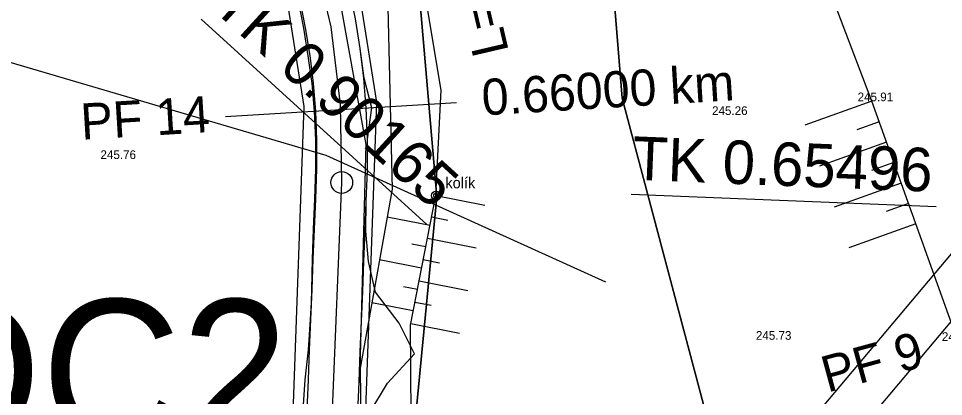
# Model space of a CAD drawing. Extents: x -555887 to -552101, y -1100251 to -1096546.
# Drawn here: x -554275.9 to -554212, y -1096964.9 to -1096938.8 of the extents above; entities that cross this region are included whole.
import ezdxf

# ---------------------------------------------------------------- set-up
doc = ezdxf.new("R2010")
doc.units = 0
for name, color, linetype in [('PARCELY_cesty', 7, 'Continuous'), ('PARCELY_VHO', 7, 'Continuous'), ('POLYGONY_POPIS_CESTY', 7, 'Continuous'), ('POLYGONY_SITUACE_PF', 7, 'Continuous'), ('POLYGONY_SITUACE_PF_POPISY', 7, 'Continuous'), ('POLYGONY_SITUACE_PO', 7, 'Continuous'), ('ram_VC2', 7, 'Continuous'), ('vrstevnice', 7, 'Continuous'), ('Výškopis', 7, 'Continuous'), ('ZSST', 7, 'Continuous'), ('zájem', 7, 'Continuous')]:
    doc.layers.add(name, color=color, linetype=linetype)

msp = doc.modelspace()

# ---------------------------------------------------------------- linework, layer by layer
for p, q in [((-554263.284, -1096938.802), (-554247.684, -1096952.999)), ((-554233.587, -1096950.895), (-554212.512, -1096951.742))]:
    msp.add_line(p, q)
at = {"layer": 'PARCELY_cesty'}
for points in [[(-554235.26, -1097250.21), (-554222.331, -1097095.103), (-554222.177, -1097088.532), (-554223.591, -1097078.803), (-554226.634, -1097069.372), (-554233.336, -1097058.257), (-554245.88, -1097042.059), (-554250.33, -1097033.26), (-554252.753, -1097025.27), (-554253.637, -1097013.936), (-554251.138, -1096944.546), (-554252.472, -1096936.15), (-554254.994, -1096928.042), (-554262.23, -1096914.12), (-554265.12, -1096907.97)], [(-554240.159, -1097243.281), (-554227.326, -1097094.829), (-554227.186, -1097088.835), (-554228.479, -1097079.938), (-554231.215, -1097071.458), (-554237.468, -1097061.088), (-554250.126, -1097044.743), (-554254.988, -1097035.128), (-554257.695, -1097026.201), (-554258.644, -1097014.04), (-554256.152, -1096944.852), (-554257.354, -1096937.291), (-554259.63, -1096929.971), (-554262.611, -1096924.345), (-554273.038, -1096923.935)]]:
    msp.add_lwpolyline(points, dxfattribs=at)
at = {"layer": 'PARCELY_VHO'}
for points in [[(-554130.46, -1097180.06), (-554159.17, -1097101.34), (-554159.64, -1097082.93), (-554163.72, -1097067.19), (-554173.74, -1097050.79), (-554190.63, -1097034.96), (-554197.16, -1097028.05), (-554217.46, -1096987.98), (-554225.33, -1096977.64), (-554234.21, -1096944.26), (-554236.99, -1096909.92), (-554235.22, -1096898.62), (-554228.6, -1096882.13), (-554225.73, -1096869.26), (-554224.9, -1096864.61), (-554220.11, -1096846.63), (-554200.4, -1096831.93), (-554179.17, -1096807.62), (-554142.08, -1096773.53), (-554110.69, -1096747.36), (-554089.18, -1096729.49)], [(-554235.26, -1097250.21), (-554222.331, -1097095.103), (-554222.177, -1097088.532), (-554223.591, -1097078.803), (-554226.634, -1097069.372), (-554233.336, -1097058.257), (-554245.88, -1097042.059), (-554250.33, -1097033.26), (-554252.753, -1097025.27), (-554253.637, -1097013.936), (-554251.138, -1096944.546), (-554252.472, -1096936.15), (-554254.994, -1096928.042), (-554262.23, -1096914.12), (-554265.12, -1096907.97), (-554264.18, -1096901.52), (-554256.593, -1096884.824), (-554225.08, -1096837.14), (-554208.2, -1096823.7)], [(-554200.4, -1096831.93), (-554220.11, -1096846.63), (-554224.9, -1096864.61), (-554233.29, -1096868.06), (-554243.42, -1096872.22), (-554247.48, -1096879.5), (-554255.66, -1096892.57), (-554260.45, -1096913.44), (-554248.68, -1096931.61), (-554247, -1096951.09), (-554248.74, -1096969.23), (-554247.82, -1097012.49), (-554234.69, -1097042.48), (-554228.63, -1097050.04), (-554218.79, -1097074.22), (-554216.52, -1097103.52), (-554219.47, -1097120.44), (-554219.42, -1097159.44)]]:
    msp.add_lwpolyline(points, dxfattribs=at)
at = {"layer": 'POLYGONY_SITUACE_PF'}
for p, q in [((-554253.622, -1096945.055), (-554245.637, -1096944.571)), ((-554261.607, -1096945.539), (-554253.622, -1096945.055))]:
    msp.add_line(p, q, dxfattribs=at)
at = {"layer": 'POLYGONY_SITUACE_PO'}
for p, q in [((-554254.299, -1096939.346), (-554255.527, -1096934.095)), ((-554252.618, -1096938.787), (-554253.03, -1096936.758)), ((-554252.618, -1096938.787), (-554253.03, -1096936.758)), ((-554252.618, -1096938.787), (-554253.03, -1096936.758)), ((-554256.188, -1096939.439), (-554256.55, -1096937.548)), ((-554256.061, -1096939.416), (-554256.445, -1096937.524)), ((-554256.061, -1096939.416), (-554256.445, -1096937.524)), ((-554252.287, -1096940.83), (-554252.618, -1096938.787)), ((-554252.287, -1096940.83), (-554252.618, -1096938.787)), ((-554252.287, -1096940.83), (-554252.618, -1096938.787)), ((-554255.889, -1096941.34), (-554256.188, -1096939.439)), ((-554255.752, -1096941.321), (-554256.061, -1096939.416)), ((-554255.752, -1096941.321), (-554256.061, -1096939.416)), ((-554253.645, -1096944.699), (-554254.299, -1096939.346)), ((-554252.038, -1096942.885), (-554252.287, -1096940.83)), ((-554252.038, -1096942.885), (-554252.287, -1096940.83)), ((-554252.026, -1096942.884), (-554252.287, -1096940.83)), ((-554252.287, -1096940.83), (-554252.287, -1096940.83)), ((-554255.622, -1096943.247), (-554255.889, -1096941.34)), ((-554255.52, -1096943.237), (-554255.752, -1096941.321)), ((-554255.52, -1096943.237), (-554255.752, -1096941.321)), ((-554251.875, -1096944.949), (-554252.038, -1096942.885)), ((-554251.875, -1096944.949), (-554252.038, -1096942.885)), ((-554251.501, -1096944.926), (-554252.026, -1096942.884)), ((-554255.454, -1096945.166), (-554255.622, -1096943.247)), ((-554255.369, -1096945.161), (-554255.52, -1096943.237)), ((-554255.369, -1096945.161), (-554255.52, -1096943.237)), ((-554253.571, -1096950.091), (-554253.645, -1096944.699)), ((-554255.359, -1096947.171), (-554255.454, -1096945.166)), ((-554255.291, -1096947.169), (-554255.369, -1096945.161)), ((-554255.291, -1096947.169), (-554255.369, -1096945.161)), ((-554251.791, -1096947.103), (-554251.875, -1096944.949)), ((-554251.791, -1096947.103), (-554251.875, -1096944.949)), ((-554251.791, -1096947.103), (-554251.501, -1096944.926)), ((-554255.357, -1096949.178), (-554255.359, -1096947.171)), ((-554255.298, -1096949.18), (-554255.291, -1096947.169)), ((-554255.298, -1096949.18), (-554255.291, -1096947.169)), ((-554251.799, -1096949.259), (-554251.791, -1096947.103)), ((-554251.799, -1096949.259), (-554251.791, -1096947.103)), ((-554251.799, -1096949.259), (-554251.791, -1096947.103)), ((-554251.791, -1096947.103), (-554251.791, -1096947.103)), ((-554255.426, -1096951.229), (-554255.357, -1096949.178)), ((-554255.368, -1096951.231), (-554255.298, -1096949.18)), ((-554255.368, -1096951.231), (-554255.298, -1096949.18)), ((-554251.871, -1096951.372), (-554251.799, -1096949.259)), ((-554251.871, -1096951.372), (-554251.799, -1096949.259)), ((-554251.871, -1096951.372), (-554251.799, -1096949.259)), ((-554256.141, -1097013.988), (-554253.571, -1096950.091)), ((-554255.524, -1096953.31), (-554255.426, -1096951.229)), ((-554255.452, -1096953.313), (-554255.368, -1096951.231)), ((-554255.452, -1096953.313), (-554255.368, -1096951.231)), ((-554251.955, -1096953.453), (-554251.871, -1096951.372)), ((-554251.955, -1096953.453), (-554251.871, -1096951.372)), ((-554251.899, -1096953.456), (-554251.871, -1096951.372)), ((-554251.871, -1096951.372), (-554251.871, -1096951.372)), ((-554255.581, -1096955.393), (-554255.524, -1096953.31)), ((-554255.536, -1096955.394), (-554255.452, -1096953.313)), ((-554255.536, -1096955.394), (-554255.452, -1096953.313)), ((-554252.038, -1096955.535), (-554251.955, -1096953.453)), ((-554252.038, -1096955.535), (-554251.955, -1096953.453)), ((-554251.72, -1096955.548), (-554251.899, -1096953.456)), ((-554255.631, -1096957.476), (-554255.581, -1096955.393)), ((-554255.619, -1096957.476), (-554255.536, -1096955.394)), ((-554255.619, -1096957.476), (-554255.536, -1096955.394)), ((-554252.122, -1096957.617), (-554252.038, -1096955.535)), ((-554252.122, -1096957.617), (-554252.038, -1096955.535)), ((-554251.24, -1096957.652), (-554251.72, -1096955.548)), ((-554255.703, -1096959.558), (-554255.619, -1096957.476)), ((-554255.703, -1096959.558), (-554255.619, -1096957.476)), ((-554255.655, -1096958.369), (-554255.631, -1096957.476)), ((-554252.206, -1096959.698), (-554252.122, -1096957.617)), ((-554252.206, -1096959.698), (-554252.122, -1096957.617)), ((-554249.594, -1096959.803), (-554251.24, -1096957.652)), ((-554255.719, -1096959.557), (-554255.655, -1096958.369)), ((-554255.867, -1096961.636), (-554255.719, -1096959.557)), ((-554255.787, -1096961.639), (-554255.703, -1096959.558)), ((-554255.787, -1096961.639), (-554255.703, -1096959.558)), ((-554252.29, -1096961.78), (-554252.206, -1096959.698)), ((-554252.29, -1096961.78), (-554252.206, -1096959.698)), ((-554248.543, -1096961.931), (-554249.594, -1096959.803)), ((-554256.092, -1096963.712), (-554255.867, -1096961.636)), ((-554255.87, -1096963.721), (-554255.787, -1096961.639)), ((-554255.87, -1096963.721), (-554255.787, -1096961.639)), ((-554252.373, -1096963.862), (-554252.29, -1096961.78)), ((-554252.373, -1096963.862), (-554252.29, -1096961.78)), ((-554250.398, -1096963.941), (-554248.543, -1096961.931)), ((-554256.244, -1096965.791), (-554256.092, -1096963.712)), ((-554255.954, -1096965.803), (-554255.87, -1096963.721)), ((-554255.954, -1096965.803), (-554255.87, -1096963.721)), ((-554252.457, -1096965.943), (-554252.373, -1096963.862)), ((-554252.457, -1096965.943), (-554252.373, -1096963.862)), ((-554251.631, -1096965.977), (-554250.398, -1096963.941))]:
    msp.add_line(p, q, dxfattribs=at)
msp.add_circle((-554253.571, -1096950.091), 0.75, dxfattribs=at)
at = {"layer": 'ram_VC2'}
for points in [[(-554299.227, -1097059.305), (-554179.469, -1096916.988), (-554128.97, -1096959.483), (-554248.728, -1097101.8)], [(-554295, -1097058.941), (-554179.106, -1096921.215), (-554133.197, -1096959.847), (-554249.092, -1097097.572)]]:
    msp.add_lwpolyline(points, close=True, dxfattribs=at)
at = {"layer": 'vrstevnice'}
msp.add_lwpolyline([(-554527.775, -1096787.581), (-554505.228, -1096794.014), (-554472.373, -1096810.738), (-554455.624, -1096823.603), (-554438.23, -1096842.258), (-554427.279, -1096858.982), (-554416.328, -1096882.783), (-554406.02, -1096908.513), (-554391.848, -1096926.524), (-554380.252, -1096936.816), (-554369.301, -1096940.675), (-554352.552, -1096940.675), (-554329.69, -1096938.394), (-554315.485, -1096937.666), (-554303.83, -1096937.303), (-554295.452, -1096938.03), (-554276.876, -1096941.667), (-554254.658, -1096948.213), (-554235.354, -1096956.942)], dxfattribs=at)
at = {"layer": 'ZSST'}
for p, q in [((-554216.96, -1096944.48), (-554221.581, -1096946.136)), ((-554216.454, -1096945.892), (-554217.993, -1096946.443)), ((-554215.948, -1096947.304), (-554220.569, -1096948.96)), ((-554215.442, -1096948.716), (-554216.981, -1096949.268)), ((-554214.936, -1096950.128), (-554219.557, -1096951.784)), ((-554247.06, -1096950.99), (-554243.696, -1096951.656)), ((-554214.43, -1096951.54), (-554215.969, -1096952.092)), ((-554247.472, -1096953.07), (-554250.429, -1096952.485)), ((-554247.351, -1096952.461), (-554246.231, -1096952.683)), ((-554213.924, -1096952.953), (-554218.545, -1096954.608)), ((-554247.763, -1096954.542), (-554248.739, -1096954.349)), ((-554247.643, -1096953.933), (-554244.278, -1096954.599)), ((-554248.055, -1096956.013), (-554250.959, -1096955.438)), ((-554247.934, -1096955.404), (-554246.814, -1096955.626)), ((-554248.225, -1096956.876), (-554244.861, -1096957.542)), ((-554248.346, -1096957.485), (-554249.304, -1096957.295)), ((-554248.637, -1096958.956), (-554251.489, -1096958.391)), ((-554248.517, -1096958.347), (-554247.396, -1096958.569)), ((-554248.808, -1096959.819), (-554245.444, -1096960.485))]:
    msp.add_line(p, q, dxfattribs=at)
for points in [[(-554252.3, -1096962.91), (-554251.89, -1096947.46), (-554254.33, -1096933.96), (-554258.67, -1096923.35), (-554264.63, -1096912.03), (-554266.17, -1096905.46), (-554264.87, -1096893.9), (-554261.55, -1096884.27), (-554256.75, -1096876.83), (-554246.08, -1096863.72), (-554231.7, -1096845.76), (-554223.08, -1096831.86), (-554218.37, -1096827.54), (-554210.29, -1096822.07), (-554198.72, -1096814.57), (-554189.47, -1096809.37), (-554178.38, -1096802.21), (-554170.29, -1096795.75), (-554158.02, -1096787.64), (-554138.36, -1096771.85), (-554116.97, -1096752.81), (-554099.76, -1096736.76), (-554079.01, -1096718.05)], [(-554188, -1096818.64), (-554188.82, -1096814.37), (-554190.64, -1096810.55), (-554203.49, -1096818.78), (-554212.9, -1096826.01), (-554219.76, -1096831.63), (-554225.59, -1096837.42), (-554232.61, -1096848.4), (-554241.45, -1096861.76), (-554255.58, -1096885.74), (-554259.15, -1096891.03), (-554264.18, -1096901.52), (-554262.23, -1096914.12), (-554254.91, -1096925), (-554250.45, -1096935.08), (-554250.08, -1096950.54), (-554252.3, -1096962.91)], [(-554248.75, -1096969.32), (-554248.83, -1096959.93), (-554247.06, -1096950.99), (-554246.71, -1096943.72), (-554248.72, -1096931.57), (-554260.49, -1096913.37), (-554262.48, -1096905.88), (-554262.15, -1096901.68), (-554255.84, -1096892.45), (-554252.43, -1096885.13), (-554239.88, -1096862.77), (-554230.92, -1096848.31), (-554223.97, -1096838.55), (-554218.79, -1096832.76), (-554212.02, -1096827.16), (-554202.06, -1096819.83), (-554190.67, -1096813.97), (-554190.64, -1096810.55)], [(-554189.44, -1097009.07), (-554189.29, -1097003.58), (-554192.09, -1096996.42), (-554196.79, -1096989.85), (-554203.75, -1096978.28), (-554211.03, -1096961.03), (-554216.96, -1096944.48), (-554220.11, -1096936.16), (-554213.34, -1096924.57), (-554209.99, -1096922.37), (-554215.63, -1096918.27), (-554219.45, -1096911.72), (-554215.85, -1096907.48), (-554214.43, -1096900.67), (-554212.25, -1096888.64), (-554208.26, -1096873.22), (-554195.25, -1096867.45)], [(-554252.3, -1096962.91), (-554252.15, -1096975.19), (-554251.67, -1096987.35), (-554251.95, -1096998.96), (-554250.9, -1097012.23), (-554249.88, -1097021.55), (-554248.64, -1097027.57), (-554246.07, -1097036.01), (-554240.86, -1097045.62), (-554233.57, -1097053.76), (-554226.53, -1097064.63), (-554223.28, -1097073.72), (-554220.82, -1097084.32), (-554219.54, -1097095.27), (-554223.32, -1097113.64)]]:
    msp.add_lwpolyline(points, dxfattribs=at)
for radius in [0.3, 0.15]:
    msp.add_circle((-554247.06, -1096950.99), radius, dxfattribs=at)
at = {"layer": 'zájem'}
for points in [[(-554197.16, -1097028.05), (-554217.46, -1096987.98), (-554225.33, -1096977.64), (-554234.21, -1096944.26), (-554236.99, -1096909.92), (-554235.22, -1096898.62), (-554228.6, -1096882.13), (-554225.73, -1096869.26), (-554224.9, -1096864.61), (-554233.29, -1096868.06), (-554243.42, -1096872.22), (-554247.48, -1096879.5), (-554255.66, -1096892.57), (-554260.45, -1096913.44), (-554248.68, -1096931.61), (-554247, -1096951.09), (-554248.74, -1096969.23), (-554247.82, -1097012.49)], [(-554247.82, -1097012.49), (-554248.74, -1096969.23), (-554247, -1096951.09), (-554248.68, -1096931.61), (-554260.45, -1096913.44), (-554255.66, -1096892.57), (-554247.48, -1096879.5), (-554243.42, -1096872.22), (-554233.29, -1096868.06), (-554224.9, -1096864.61), (-554225.73, -1096869.26), (-554228.6, -1096882.13), (-554235.22, -1096898.62), (-554236.99, -1096909.92), (-554234.21, -1096944.26), (-554225.33, -1096977.64), (-554217.46, -1096987.98), (-554197.16, -1097028.05)]]:
    msp.add_lwpolyline(points, dxfattribs=at)

# ---------------------------------------------------------------- texts
for s, height, rotation, p in [('L=26.976', 2.5, 103.15301, (-554242.02, -1096941.035)), ('TK 0.90165', 3, 317.69467, (-554262.611, -1096938.063)), ('TK 0.65496', 3, 357.69671, (-554233.547, -1096949.896))]:
    msp.add_text(s, height=height, rotation=rotation).set_placement(p)
at = {"layer": 'POLYGONY_POPIS_CESTY'}
msp.add_text('DC2', height=10, rotation=360, dxfattribs=at).set_placement((-554283.973, -1096968.16))
at = {"layer": 'POLYGONY_SITUACE_PF_POPISY'}
for s, rotation, p in [('0.66000 km', 3.47049, (-554243.826, -1096945.463)), ('PF 14', 3.47049, (-554271.529, -1096947.143)), ('PF 9', 15.27101, (-554220.026, -1096964.607))]:
    msp.add_text(s, height=2.5, rotation=rotation, dxfattribs=at).set_placement(p)
at = {"layer": 'Výškopis'}
for s, p in [('245.91', (-554217.94, -1096944.48)), ('245.26', (-554227.994, -1096945.43)), ('245.76', (-554270.231, -1096948.47)), ('245.73', (-554224.966, -1096960.95)), ('246.05', (-554212.12, -1096961.03))]:
    msp.add_text(s, height=0.6, dxfattribs=at).set_placement(p)
at = {"layer": 'ZSST'}
msp.add_text('kolík', height=0.75, dxfattribs=at).set_placement((-554246.41, -1096950.488))

doc.saveas('drawing.dxf')
